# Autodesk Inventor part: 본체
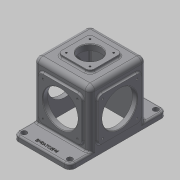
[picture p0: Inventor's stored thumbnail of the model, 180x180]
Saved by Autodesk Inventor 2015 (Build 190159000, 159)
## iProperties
Created: 2018-09
Part Number: 본체
Material: 일반
Document SubType Name: Modeling
Designer: mduedu
Density: 1 g/cm^3
Appearance: 기본값
Author: mduedu
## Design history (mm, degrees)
sketch "스케치1"
  geometry: L1 (90, 52.5)-(-90, 52.5); L2 (-90, 52.5)-(-90, -52.5); L3 (-90, -52.5)-(90, -52.5); L4 (90, -52.5)-(90, 52.5); L5 (90, 52.5)-(-90, -52.5); L6 (-90, 52.5)-(90, -52.5); 1 further point
  constraints: 12 end point, 2 midpoint, 2 parallel, 1 horizontal, 1 perpendicular
  dimensions: "d0" = 180 distance of L3.end L2.end; "d1" = 105 distance of L2.end L1.end
extrude "돌출1" new body sketch "스케치1" distance "d2" = 10; taper "d3" = 0 deg
sketch "스케치2"
  geometry: L1 (-52.5, -52.5)-(52.5, -52.5); L2 (52.5, -52.5)-(52.5, 52.5); L3 (52.5, 52.5)-(-52.5, 52.5); L4 (-52.5, 52.5)-(-52.5, -52.5); L5 (-52.5, -52.5)-(52.5, 52.5); L6 (52.5, -52.5)-(-52.5, 52.5); 1 further point
  constraints: 12 end point, 2 midpoint, 2 parallel, 1 horizontal, 1 perpendicular
  dimensions: "d4" = 105 distance of L3.end L2.end; "d5" = 105 distance of L2.end L1.end
extrude "돌출2" join sketch "스케치2" distance "d6" = 105; taper "d7" = 0 deg
node "작업 평면1"
sketch "스케치3"
  geometry: L1 (-52.5, 52.5)-(52.5, 52.5) reference; L2 (52.5, 52.5)-(52.5, -52.5) reference; L3 (52.5, -52.5)-(-52.5, -52.5) reference; L4 (-52.5, -52.5)-(-52.5, 52.5) reference; L5 (46.5, 46.5)-(-46.5, 46.5); L6 (-46.5, 46.5)-(-46.5, -46.5); L7 (-46.5, -46.5)-(46.5, -46.5); L8 (46.5, -46.5)-(46.5, 46.5); 1 further point
  constraints: 8 end point, 3 other
  dimensions: "d9" = 6 distance between parallel lines of L5 L1
extrude "돌출3" cut sketch "스케치3" stored distance "d10" = 105; taper "d11" = 0 deg
fillet "모깎기1" dims "d12" = 9
fillet "모깎기2" dims "d13" = 9
fillet "모깎기3" dims "d14" = 3
fillet "모깎기4" dims "d15" = 3
sketch "스케치4"
  geometry: L1 (-30, -30)-(30, -30); L2 (30, -30)-(30, 30); L3 (30, 30)-(-30, 30); L4 (-30, 30)-(-30, -30); L5 (-30, -30)-(30, 30); L6 (30, -30)-(-30, 30); 1 further point
  constraints: 12 end point, 2 midpoint, 2 parallel, 1 horizontal, 1 perpendicular
  dimensions: "d16" = 60 distance of L3.end L2.end; "d17" = 60 distance of L2.end L1.end
extrude "돌출4" join sketch "스케치4" distance "d18" = 5; taper "d19" = 0 deg
fillet "모깎기5" dims "d20" = 8
fillet "모깎기6" dims "d21" = 3
sketch "스케치5"
  geometry: C1 r 20 at (0, 0); 1 further point
  constraints: 1 centre point, 1 coincident
  dimensions: "d22" = 40 diameter of C1
extrude "돌출5" cut sketch "스케치5" stored distance "d23" = 5; taper "d24" = 0 deg
sketch "스케치6"
  geometry: L1 (50, 17.5)-(130, 17.5); L2 (130, 17.5)-(130, 97.5); L3 (130, 97.5)-(50, 97.5); L4 (50, 97.5)-(50, 17.5); L5 (50, 17.5)-(130, 97.5); L6 (130, 17.5)-(50, 97.5); L7 (0, 0)-(180, 0) reference; 4 further points
  constraints: 12 end point, 4 midpoint, 2 parallel, 1 horizontal, 1 perpendicular, 1 vertical alignment
  dimensions: "d25" = 80 distance of L3.end L2.end; "d26" = 80 distance of L2.end L1.end; "d27" = 57.5 distance of point (90, 0) point (90, 57.5)
extrude "돌출6" join sketch "스케치6" distance "d28" = 3; taper "d29" = 0 deg
fillet "모깎기7" dims "d30" = 8
sketch "스케치7"
  geometry: C1 r 32.5 at (90, 57.5); 1 further point
  constraints: 1 centre point, 1 vertical alignment
  dimensions: "d32" = 65 diameter of C1; "d33" = 57.5 distance of C1.centre point (90, 0)
extrude "돌출7" cut sketch "스케치7" stored distance "d34" = 3; taper "d35" = 0 deg
fillet "모깎기9" dims "d36" = 3
sketch "스케치8"
  geometry: L1 (3.5, 7.5)-(83.5, 7.5); L2 (83.5, 7.5)-(83.5, 87.5); L3 (83.5, 87.5)-(3.5, 87.5); L4 (3.5, 87.5)-(3.5, 7.5); L5 (3.5, 7.5)-(83.5, 87.5); L6 (83.5, 7.5)-(3.5, 87.5); L7 (-9, -10)-(96, -10) reference; C1 r 32.5 at (43.5, 47.5); 4 further points
  constraints: 12 end point, 4 midpoint, 2 parallel, 1 centre point, 1 coincident, 1 horizontal, 1 perpendicular, 1 vertical alignment
  dimensions: "d37" = 80 distance of L3.end L2.end; "d38" = 80 distance of L2.end L1.end; "d39" = 57.5 distance from line of point (43.5, 47.5) L7; "d40" = 65 diameter of C1
extrude "돌출8" join sketch "스케치8" distance "d41" = 3; taper "d42" = 0 deg
fillet "모깎기10" dims "d43" = 8
extrude "돌출9" cut sketch "스케치8" stored distance "d44" = 3; taper "d45" = 0 deg
fillet "모깎기11" dims "d46" = 3
sketch "스케치9"
  geometry: L1 (50, 89.5)-(50, 25.5) reference; L2 (58, 17.5)-(122, 17.5) reference; L3 (130, 25.5)-(130, 89.5) reference; L4 (122, 97.5)-(58, 97.5) reference; C1 r 32.5 at (90, 57.5) reference; A1 r 8 centre (58, 89.5) between (58, 97.5) and (50, 89.5) reference; A2 r 8 centre (58, 25.5) between (50, 25.5) and (58, 17.5) reference; A3 r 8 centre (122, 25.5) between (122, 17.5) and (130, 25.5) reference; A4 r 8 centre (122, 89.5) between (130, 89.5) and (122, 97.5) reference; 5 further points
  constraints: 4 coincident
hole "구멍1" sketch "스케치9" at (58, 89.5), (122, 89.5), (122, 25.5), (58, 25.5) diameter "d47" = 3.242; stored, may be unused: countersink angle "d51" = 90 deg, drill point angle "d53" = 118 deg; dims "d48" = 6, "d49" = 4, "d50" = 2, "d52" = 9
sketch "스케치10"
  geometry: L1 (11.5, 7.5)-(75.5, 7.5) reference; L2 (83.5, 15.5)-(83.5, 79.5) reference; L3 (75.5, 87.5)-(11.5, 87.5) reference; L4 (3.5, 79.5)-(3.5, 15.5) reference; C1 r 32.5 at (43.5, 47.5) reference; A1 r 8 centre (11.5, 15.5) between (3.5, 15.5) and (11.5, 7.5) reference; A2 r 8 centre (75.5, 15.5) between (75.5, 7.5) and (83.5, 15.5) reference; A3 r 8 centre (75.5, 79.5) between (83.5, 79.5) and (75.5, 87.5) reference; A4 r 8 centre (11.5, 79.5) between (11.5, 87.5) and (3.5, 79.5) reference; 5 further points
  constraints: 4 coincident
hole "구멍2" sketch "스케치10" at (11.5, 79.5), (75.5, 79.5), (75.5, 15.5), (11.5, 15.5) diameter "d54" = 3.242; stored, may be unused: countersink angle "d58" = 90 deg, drill point angle "d60" = 118 deg; dims "d55" = 6, "d56" = 4, "d57" = 2, "d59" = 9
sketch "스케치11"
  geometry: L1 (22, 30)-(-22, 30) reference; L2 (-30, 22)-(-30, -22) reference; L3 (-22, -30)-(22, -30) reference; L4 (30, -22)-(30, 22) reference; C1 r 20 at (0, 0) reference; A1 r 8 centre (22, 22) between (30, 22) and (22, 30) reference; A2 r 8 centre (-22, 22) between (-22, 30) and (-30, 22) reference; A3 r 8 centre (-22, -22) between (-30, -22) and (-22, -30) reference; A4 r 8 centre (22, -22) between (22, -30) and (30, -22) reference; 5 further points
  constraints: 4 coincident
hole "구멍3" sketch "스케치11" at (-22, 22), (22, 22), (22, -22), (-22, -22) diameter "d61" = 3.242; stored, may be unused: countersink angle "d65" = 90 deg, drill point angle "d67" = 118 deg; dims "d62" = 7, "d63" = 4, "d64" = 2, "d66" = 9
fillet "모깎기12" dims "d68" = 10
sketch "스케치12"
  geometry: L1 (-90, 42.5)-(-90, -42.5) reference; L2 (-80, -52.5)-(-43.5, -52.5) reference; L3 (-52.5, -43.5)-(-52.5, 43.5) reference; L4 (-43.5, 52.5)-(-80, 52.5) reference; A1 r 10 centre (-80, 42.5) between (-80, 52.5) and (-90, 42.5) reference; A2 r 10 centre (-80, -42.5) between (-90, -42.5) and (-80, -52.5) reference; A3 r 9 centre (-43.5, -43.5) between (-52.5, -43.5) and (-43.5, -52.5) reference; A4 r 9 centre (-43.5, 43.5) between (-43.5, 52.5) and (-52.5, 43.5) reference; 3 further points
  constraints: 2 coincident
hole "구멍4" sketch "스케치12" at (-80, 42.5), (-80, -42.5) diameter "d70" = 10; stored, may be unused: countersink angle "d74" = 90 deg, drill point angle "d76" = 118 deg; dims "d71" = 6, "d72" = 4, "d73" = 2, "d75" = 9
fillet "모깎기13" dims "d77" = 3
fillet "모깎기14" dims "d78" = 3
chamfer "모따기1" distance "d79" = 1; stored, may be unused: second distance "d80" = 2, angle "d81" = 45 deg
sketch "스케치13"
  geometry: L1 (90, -42.5)-(90, 42.5) reference; 2 further points
  constraints: 1 horizontal alignment, 1 other
  dimensions: "d82" = 10 distance from line of point (80, 0) L1
feature "엠보싱1" sketch "스케치13" dims "d83" = 0.5, "d84" = 0
node "솔리드1"
mirror "대칭1"
mirror "대칭2"
mirror "대칭3"
node "투영된 루프1"
node "투영된 루프2"
node "투영된 루프3"
node "투영된 루프4"
node "투영된 루프5"
other parameters: "d8" = -6
